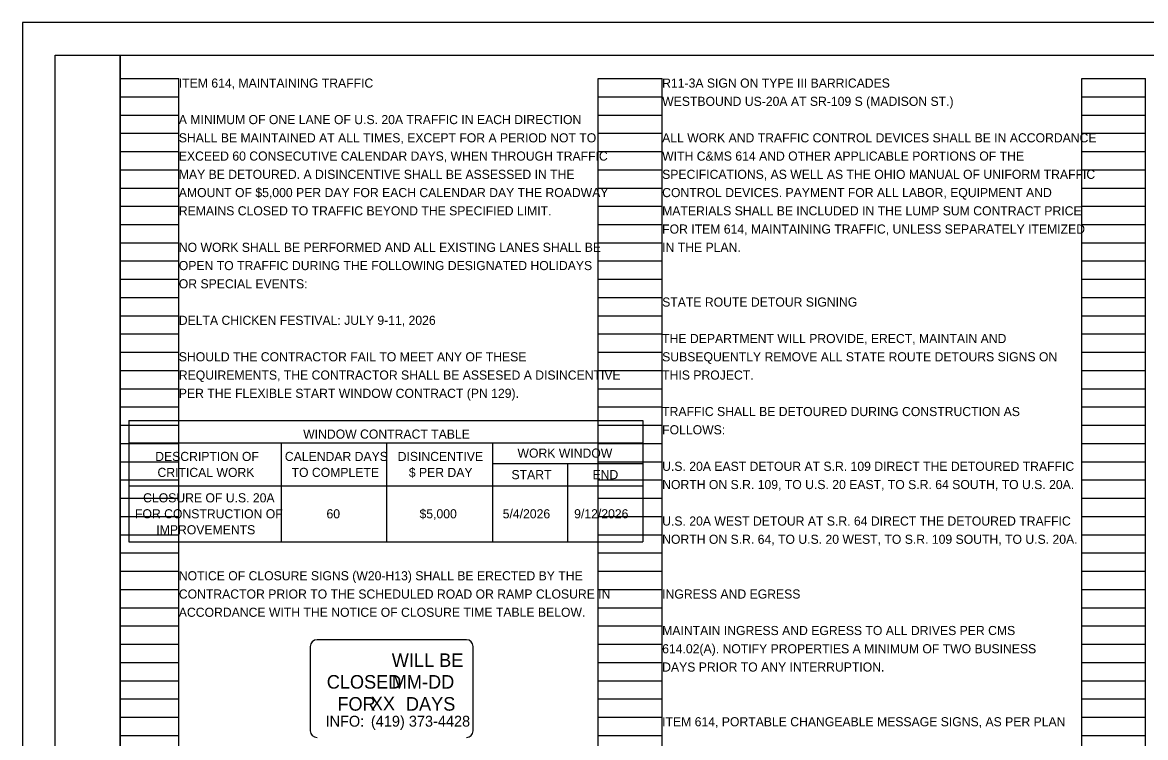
# Model space of a CAD drawing. Extents: x 0 to 42, y 0 to 22.
# Drawn here: x 0 to 17.24, y 11.03 to 22 of the extents above; entities that cross this region are included whole.
import ezdxf

# ---------------------------------------------------------------- set-up
doc = ezdxf.new("R2010")
doc.units = 0
for name, color, linetype in [('SH_Border', 7, 'Continuous'), ('SH_Cut_Line', 7, 'Continuous'), ('SH_Data', 7, 'Continuous'), ('SH_Text', 7, 'Continuous'), ('SN_P_Signs', 7, 'Continuous')]:
    doc.layers.add(name, color=color, linetype=linetype)

msp = doc.modelspace()

# ---------------------------------------------------------------- linework, layer by layer
at = {"layer": 'SH_Border'}
for points in [[(0.5, 21.5), (1.5, 21.5), (1.5, 0.5), (0.5, 0.5)], [(1.5, 21.5), (33.5, 21.5), (33.5, 0.5), (1.5, 0.5)]]:
    msp.add_lwpolyline(points, close=True, dxfattribs=at)
at = {"layer": 'SH_Cut_Line'}
msp.add_lwpolyline([(0, 0), (34, 0), (34, 22), (0, 22)], close=True, dxfattribs=at)
at = {"layer": 'SH_Data'}
for p, q in [((1.5, 0.98), (1.5, 21.14)), ((1.5, 21.14), (2.4, 21.14)), ((2.4, 0.98), (2.4, 21.14)), ((8.84, 0.98), (8.84, 21.14)), ((8.84, 21.14), (9.82, 21.14)), ((9.82, 0.98), (9.82, 21.14)), ((16.26, 0.98), (16.26, 21.14)), ((16.26, 21.14), (17.24, 21.14)), ((17.24, 0.98), (17.24, 21.14)), ((1.5, 20.86), (2.4, 20.86)), ((8.84, 20.86), (9.82, 20.86)), ((16.26, 20.86), (17.24, 20.86)), ((1.5, 20.58), (2.4, 20.58)), ((8.84, 20.58), (9.82, 20.58)), ((16.26, 20.58), (17.24, 20.58)), ((1.5, 20.3), (2.4, 20.3)), ((8.84, 20.3), (9.82, 20.3)), ((16.26, 20.3), (17.24, 20.3)), ((1.5, 20.02), (2.4, 20.02)), ((8.84, 20.02), (9.82, 20.02)), ((16.26, 20.02), (17.24, 20.02)), ((1.5, 19.74), (2.4, 19.74)), ((8.84, 19.74), (9.82, 19.74)), ((16.26, 19.74), (17.24, 19.74)), ((1.5, 19.46), (2.4, 19.46)), ((8.84, 19.46), (9.82, 19.46)), ((16.26, 19.46), (17.24, 19.46)), ((1.5, 19.18), (2.4, 19.18)), ((8.84, 19.18), (9.82, 19.18)), ((16.26, 19.18), (17.24, 19.18)), ((1.5, 18.9), (2.4, 18.9)), ((8.84, 18.9), (9.82, 18.9)), ((16.26, 18.9), (17.24, 18.9)), ((1.5, 18.62), (2.4, 18.62)), ((8.84, 18.62), (9.82, 18.62)), ((16.26, 18.62), (17.24, 18.62)), ((1.5, 18.34), (2.4, 18.34)), ((8.84, 18.34), (9.82, 18.34)), ((16.26, 18.34), (17.24, 18.34)), ((1.5, 18.06), (2.4, 18.06)), ((8.84, 18.06), (9.82, 18.06)), ((16.26, 18.06), (17.24, 18.06)), ((1.5, 17.78), (2.4, 17.78)), ((8.84, 17.78), (9.82, 17.78)), ((16.26, 17.78), (17.24, 17.78)), ((1.5, 17.5), (2.4, 17.5)), ((8.84, 17.5), (9.82, 17.5)), ((16.26, 17.5), (17.24, 17.5)), ((1.5, 17.22), (2.4, 17.22)), ((8.84, 17.22), (9.82, 17.22)), ((16.26, 17.22), (17.24, 17.22)), ((1.5, 16.94), (2.4, 16.94)), ((8.84, 16.94), (9.82, 16.94)), ((16.26, 16.94), (17.24, 16.94)), ((1.5, 16.66), (2.4, 16.66)), ((8.84, 16.66), (9.82, 16.66)), ((16.26, 16.66), (17.24, 16.66)), ((1.5, 16.38), (2.4, 16.38)), ((8.84, 16.38), (9.82, 16.38)), ((16.26, 16.38), (17.24, 16.38)), ((1.5, 16.1), (2.4, 16.1)), ((8.84, 16.1), (9.82, 16.1)), ((16.26, 16.1), (17.24, 16.1)), ((1.633, 15.894), (9.522, 15.894)), ((1.633, 15.894), (1.633, 14.033)), ((9.522, 15.894), (9.522, 14.033)), ((1.5, 15.82), (2.4, 15.82)), ((8.84, 15.82), (9.82, 15.82)), ((16.26, 15.82), (17.24, 15.82)), ((1.5, 15.54), (2.4, 15.54)), ((1.633, 15.548), (9.522, 15.548)), ((3.972, 15.548), (3.972, 14.033)), ((5.586, 15.548), (5.586, 14.033)), ((7.217, 15.548), (7.217, 14.033)), ((8.84, 15.54), (9.82, 15.54)), ((16.26, 15.54), (17.24, 15.54)), ((1.5, 15.26), (2.4, 15.26)), ((7.217, 15.235), (9.522, 15.235)), ((8.369, 15.235), (8.369, 14.033)), ((8.84, 15.26), (9.82, 15.26)), ((16.26, 15.26), (17.24, 15.26)), ((1.5, 14.98), (2.4, 14.98)), ((1.633, 14.889), (9.522, 14.889)), ((8.84, 14.98), (9.82, 14.98)), ((16.26, 14.98), (17.24, 14.98)), ((1.5, 14.7), (2.4, 14.7)), ((8.84, 14.7), (9.82, 14.7)), ((16.26, 14.7), (17.24, 14.7)), ((1.5, 14.42), (2.4, 14.42)), ((8.84, 14.42), (9.82, 14.42)), ((16.26, 14.42), (17.24, 14.42)), ((1.5, 14.14), (2.4, 14.14)), ((8.84, 14.14), (9.82, 14.14)), ((16.26, 14.14), (17.24, 14.14)), ((1.633, 14.033), (9.522, 14.033)), ((1.5, 13.86), (2.4, 13.86)), ((8.84, 13.86), (9.82, 13.86)), ((16.26, 13.86), (17.24, 13.86)), ((1.5, 13.58), (2.4, 13.58)), ((8.84, 13.58), (9.82, 13.58)), ((16.26, 13.58), (17.24, 13.58)), ((1.5, 13.3), (2.4, 13.3)), ((8.84, 13.3), (9.82, 13.3)), ((16.26, 13.3), (17.24, 13.3)), ((1.5, 13.02), (2.4, 13.02)), ((8.84, 13.02), (9.82, 13.02)), ((16.26, 13.02), (17.24, 13.02)), ((1.5, 12.74), (2.4, 12.74)), ((8.84, 12.74), (9.82, 12.74)), ((16.26, 12.74), (17.24, 12.74)), ((1.5, 12.46), (2.4, 12.46)), ((8.84, 12.46), (9.82, 12.46)), ((16.26, 12.46), (17.24, 12.46)), ((1.5, 12.18), (2.4, 12.18)), ((8.84, 12.18), (9.82, 12.18)), ((16.26, 12.18), (17.24, 12.18)), ((1.5, 11.9), (2.4, 11.9)), ((8.84, 11.9), (9.82, 11.9)), ((16.26, 11.9), (17.24, 11.9)), ((1.5, 11.62), (2.4, 11.62)), ((8.84, 11.62), (9.82, 11.62)), ((16.26, 11.62), (17.24, 11.62)), ((1.5, 11.34), (2.4, 11.34)), ((8.84, 11.34), (9.82, 11.34)), ((16.26, 11.34), (17.24, 11.34)), ((1.5, 11.06), (2.4, 11.06)), ((8.84, 11.06), (9.82, 11.06)), ((16.26, 11.06), (17.24, 11.06))]:
    msp.add_line(p, q, dxfattribs=at)
at = {"layer": 'SN_P_Signs'}
for p, q in [((4.419, 12.424), (4.419, 11.132)), ((6.815, 12.528), (4.523, 12.528)), ((6.919, 11.132), (6.919, 12.424))]:
    msp.add_line(p, q, dxfattribs=at)
for centre, start, end in [((4.523, 12.424), 90, 180), ((6.815, 12.424), 0, 90), ((4.523, 11.132), 180, 270), ((6.815, 11.132), 270, 360)]:
    msp.add_arc(centre, 0.104, start, end, dxfattribs=at)

# ---------------------------------------------------------------- texts
at = {"layer": 'SH_Text'}
for s, p in [('ITEM 614, MAINTAINING TRAFFIC', (2.4, 21)), ('R11-3A SIGN ON TYPE III BARRICADES', (9.82, 21)), ('WESTBOUND US-20A AT SR-109 S (MADISON ST.)', (9.82, 20.72)), ('A MINIMUM OF ONE LANE OF U.S. 20A TRAFFIC IN EACH DIRECTION ', (2.4, 20.44)), ('SHALL BE MAINTAINED AT ALL TIMES, EXCEPT FOR A PERIOD NOT TO ', (2.4, 20.16)), ('ALL WORK AND TRAFFIC CONTROL DEVICES SHALL BE IN ACCORDANCE ', (9.82, 20.16)), ('EXCEED 60 CONSECUTIVE CALENDAR DAYS, WHEN THROUGH TRAFFIC ', (2.4, 19.88)), ('WITH C&MS 614 AND OTHER APPLICABLE PORTIONS OF THE ', (9.82, 19.88)), ('MAY BE DETOURED. A DISINCENTIVE SHALL BE ASSESSED IN THE ', (2.4, 19.6)), ('SPECIFICATIONS, AS WELL AS THE OHIO MANUAL OF UNIFORM TRAFFIC ', (9.82, 19.6)), ('AMOUNT OF $5,000 PER DAY FOR EACH CALENDAR DAY THE ROADWAY ', (2.4, 19.32)), ('CONTROL DEVICES. PAYMENT FOR ALL LABOR, EQUIPMENT AND ', (9.82, 19.32)), ('REMAINS CLOSED TO TRAFFIC BEYOND THE SPECIFIED LIMIT.', (2.4, 19.04)), ('MATERIALS SHALL BE INCLUDED IN THE LUMP SUM CONTRACT PRICE ', (9.82, 19.04)), ('FOR ITEM 614, MAINTAINING TRAFFIC, UNLESS SEPARATELY ITEMIZED ', (9.82, 18.76)), ('NO WORK SHALL BE PERFORMED AND ALL EXISTING LANES SHALL BE', (2.4, 18.48)), ('IN THE PLAN.', (9.82, 18.48)), ('OPEN TO TRAFFIC DURING THE FOLLOWING DESIGNATED HOLIDAYS', (2.4, 18.2)), ('OR SPECIAL EVENTS:', (2.4, 17.92)), ('STATE ROUTE DETOUR SIGNING', (9.82, 17.64)), ('DELTA CHICKEN FESTIVAL: JULY 9-11, 2026', (2.4, 17.36)), ('THE DEPARTMENT WILL PROVIDE, ERECT, MAINTAIN AND ', (9.82, 17.08)), ('SHOULD THE CONTRACTOR FAIL TO MEET ANY OF THESE ', (2.4, 16.8)), ('SUBSEQUENTLY REMOVE ALL STATE ROUTE DETOURS SIGNS ON ', (9.82, 16.8)), ('REQUIREMENTS, THE CONTRACTOR SHALL BE ASSESED A DISINCENTIVE ', (2.4, 16.52)), ('THIS PROJECT.', (9.82, 16.52)), ('PER THE FLEXIBLE START WINDOW CONTRACT (PN 129).', (2.4, 16.24)), ('TRAFFIC SHALL BE DETOURED DURING CONSTRUCTION AS ', (9.82, 15.96)), ('WINDOW CONTRACT TABLE', (4.309, 15.614)), ('FOLLOWS:', (9.82, 15.68)), ('DESCRIPTION OF ', (2.038, 15.271)), ('CALENDAR DAYS ', (4.028, 15.271)), ('DISINCENTIVE ', (5.76, 15.271)), ('WORK WINDOW', (7.599, 15.322)), ('$ PER DAY', (5.931, 15.026)), ('U.S. 20A EAST DETOUR AT S.R. 109 DIRECT THE DETOURED TRAFFIC ', (9.82, 15.12)), ('CRITICAL WORK', (2.073, 15.026)), ('TO COMPLETE', (4.131, 15.026)), ('START', (7.507, 14.992)), ('END', (8.751, 14.992)), ('NORTH ON S.R. 109, TO U.S. 20 EAST, TO S.R. 64 SOUTH, TO U.S. 20A.', (9.82, 14.84)), ('CLOSURE OF U.S. 20A ', (1.852, 14.636)), ('FOR CONSTRUCTION OF ', (1.728, 14.391)), ('60', (4.667, 14.391)), ('$5,000', (6.095, 14.391)), ('5/4/2026', (7.372, 14.391)), ('9/12/2026', (8.469, 14.391)), ('U.S. 20A WEST DETOUR AT S.R. 64 DIRECT THE DETOURED TRAFFIC ', (9.82, 14.28)), ('IMPROVEMENTS', (2.055, 14.146)), ('NORTH ON S.R. 64, TO U.S. 20 WEST, TO S.R. 109 SOUTH, TO U.S. 20A.', (9.82, 14)), ('NOTICE OF CLOSURE SIGNS (W20-H13) SHALL BE ERECTED BY THE ', (2.4, 13.44)), ('CONTRACTOR PRIOR TO THE SCHEDULED ROAD OR RAMP CLOSURE IN ', (2.4, 13.16)), ('INGRESS AND EGRESS', (9.82, 13.16)), ('ACCORDANCE WITH THE NOTICE OF CLOSURE TIME TABLE BELOW.', (2.4, 12.88)), ('MAINTAIN INGRESS AND EGRESS TO ALL DRIVES PER CMS ', (9.82, 12.6)), ('614.02(A). NOTIFY PROPERTIES A MINIMUM OF TWO BUSINESS ', (9.82, 12.32)), ('DAYS PRIOR TO ANY INTERRUPTION.', (9.82, 12.04)), ('ITEM 614, PORTABLE CHANGEABLE MESSAGE SIGNS, AS PER PLAN', (9.82, 11.2))]:
    msp.add_text(s, height=0.14, dxfattribs=at).set_placement(p)
at = {"layer": 'SN_P_Signs'}
for s, height, p in [('WILL BE', 0.2083, (5.669, 12.111)), ('CLOSED', 0.2083, (4.671, 11.778)), ('MM-DD', 0.2083, (5.669, 11.778)), ('FOR      DAYS', 0.20833, (4.834, 11.44)), ('XX', 0.2083, (5.347, 11.445)), ('INFO:', 0.1666, (4.652, 11.195)), ('(419) 373-4428', 0.16658, (5.349, 11.195))]:
    msp.add_text(s, height=height, dxfattribs=at).set_placement(p)

doc.saveas('drawing.dxf')
